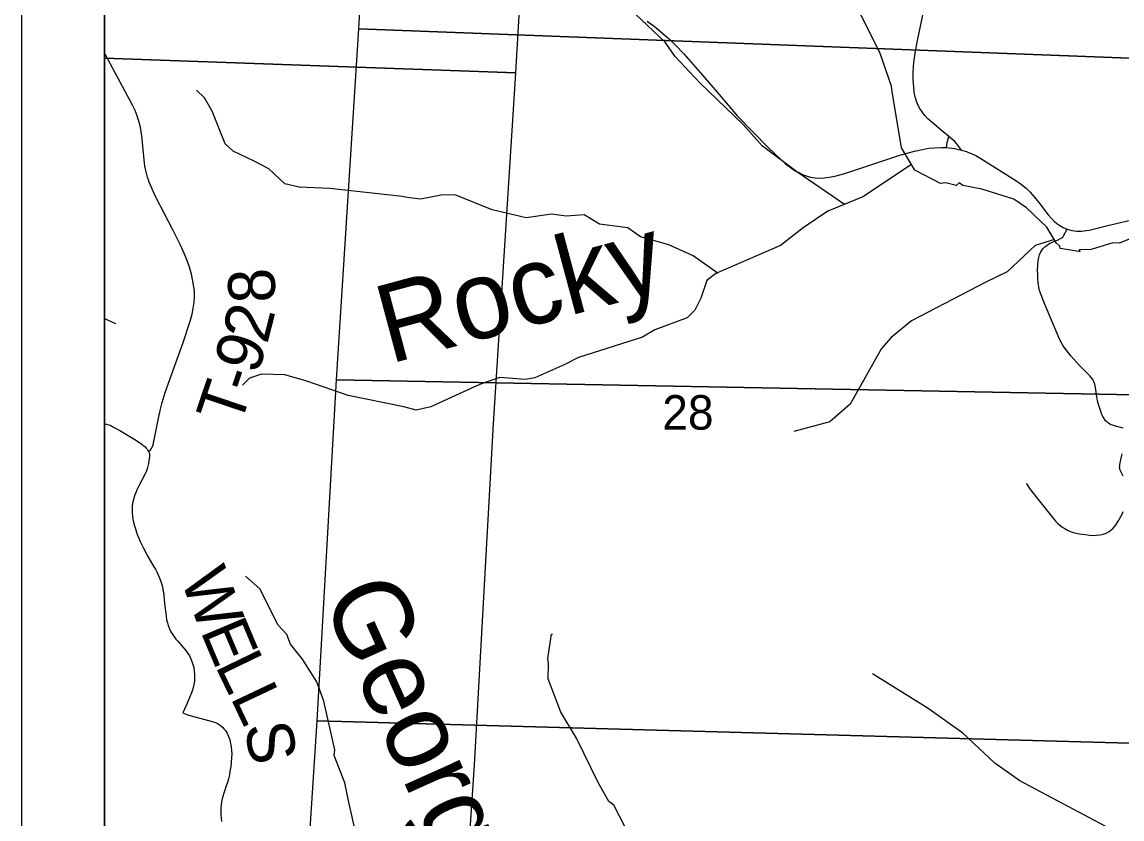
# Model space of a CAD drawing. Extents: x 0 to 34, y 0 to 22.
# Drawn here: x 23.737 to 25.071, y 17.66 to 18.626 of the extents above; entities that cross this region are included whole.
import ezdxf

# ---------------------------------------------------------------- set-up
doc = ezdxf.new("R2010")
doc.units = 0
for name, color, linetype in [('GM_X_County_Road', 7, 'Continuous'), ('GM_X_County_Road_Text', 7, 'Continuous'), ('GM_X_County_Text', 7, 'Continuous'), ('GM_X_Minor_River', 7, 'Continuous'), ('GM_X_Minor_River_Text', 7, 'Continuous'), ('GM_X_Section', 7, 'Continuous'), ('GM_X_Section_Text', 7, 'Continuous'), ('GM_X_State_Shield', 7, 'Continuous'), ('GM_X_Township_Road', 7, 'Continuous'), ('GM_X_Township_Road_Text', 7, 'Continuous'), ('SH_Cut_Line', 7, 'Continuous'), ('SH_Data', 7, 'Continuous')]:
    doc.layers.add(name, color=color, linetype=linetype)

msp = doc.modelspace()

# ---------------------------------------------------------------- linework, layer by layer
at = {"layer": 'GM_X_County_Road'}
for points in [[(24.4956, 18.6269), (24.506, 18.6191), (24.5151, 18.6116), (24.523, 18.6047), (24.5296, 18.5982), (24.5398, 18.5874), (24.5628, 18.5613), (24.583, 18.5378), (24.6046, 18.5119), (24.643, 18.4729), (24.6565, 18.4602), (24.6635, 18.454), (24.669, 18.4498), (24.6752, 18.4456), (24.6802, 18.4428), (24.6848, 18.4407), (24.6895, 18.439), (24.6938, 18.4379), (24.6994, 18.4371), (24.7051, 18.4367), (24.7102, 18.4369), (24.7164, 18.4376), (24.7232, 18.4389), (24.731, 18.441), (24.74, 18.4438), (24.8019, 18.4642), (24.8107, 18.4669), (24.8197, 18.4693), (24.8294, 18.4714), (24.8367, 18.4727), (24.8441, 18.4734), (24.8527, 18.4737), (24.8585, 18.4736), (24.8617, 18.4733), (24.865, 18.4729), (24.8684, 18.4724), (24.8717, 18.4718), (24.8769, 18.4706)], [(24.8769, 18.4706), (24.8798, 18.4697), (24.8829, 18.4687), (24.8854, 18.4678), (24.8886, 18.4665), (24.8914, 18.4652), (24.8942, 18.4639), (24.9001, 18.4605), (24.9425, 18.4338), (24.9497, 18.4287), (24.9551, 18.4244), (24.96, 18.4195), (24.965, 18.414), (24.9707, 18.4071), (24.9819, 18.3922), (24.986, 18.3875), (24.9892, 18.3844), (24.9926, 18.3816), (24.9962, 18.379), (25.0001, 18.3769), (25.0049, 18.3748), (25.0079, 18.3739), (25.0105, 18.3732), (25.0137, 18.3726), (25.0165, 18.3723), (25.0197, 18.3722), (25.0224, 18.3723), (25.0254, 18.3726), (25.0284, 18.3731), (25.0316, 18.3736), (25.056, 18.3795)], [(25.056, 18.3795), (25.0902, 18.3878), (25.1035, 18.3907), (25.112, 18.3923), (25.12, 18.3937), (25.1292, 18.3947), (25.1384, 18.3953), (25.1477, 18.3954), (25.1601, 18.395), (25.2208, 18.3915), (25.3075, 18.3848), (25.3566, 18.3838), (25.3731, 18.3836)], [(23.8372, 18.139), (23.8378, 18.1389), (23.8399, 18.1384), (23.8424, 18.1377), (23.8448, 18.1366), (23.8475, 18.1353), (23.8568, 18.1301), (23.868, 18.1235), (23.8759, 18.1185), (23.8824, 18.114), (23.8837, 18.1131), (23.885, 18.112), (23.8865, 18.1107), (23.8878, 18.1094), (23.8891, 18.1079), (23.8899, 18.1066), (23.8908, 18.1051), (23.8911, 18.1044), (23.8917, 18.1029), (23.8919, 18.1016), (23.892, 18.1002), (23.8918, 18.0986), (23.8915, 18.0967), (23.8905, 18.0907), (23.8896, 18.0858), (23.8888, 18.0832), (23.8879, 18.0806), (23.8871, 18.0788), (23.8784, 18.0628), (23.8769, 18.0596), (23.8755, 18.0564), (23.8741, 18.0527), (23.8729, 18.0488), (23.8717, 18.0442), (23.871, 18.0397), (23.8708, 18.0354), (23.8708, 18.0314), (23.8712, 18.0269), (23.8716, 18.0232), (23.8724, 18.0194), (23.8736, 18.0151), (23.8751, 18.0103), (23.8771, 18.0048), (23.879, 18), (23.8805, 17.9963), (23.8821, 17.9928), (23.8842, 17.9887), (23.89, 17.9778), (23.8973, 17.9654), (23.899, 17.9625), (23.9007, 17.9593), (23.9021, 17.9565), (23.9033, 17.9537), (23.9044, 17.9511), (23.9052, 17.9488), (23.906, 17.9465), (23.9068, 17.9439), (23.9075, 17.9411), (23.9082, 17.9377), (23.9087, 17.9347), (23.9093, 17.9304), (23.9097, 17.9264), (23.9102, 17.921), (23.9112, 17.9116), (23.9119, 17.9062), (23.9125, 17.9013), (23.9135, 17.8975), (23.9145, 17.8944), (23.9161, 17.8905), (23.9179, 17.8868), (23.9201, 17.8832), (23.9221, 17.8802), (23.9239, 17.8778), (23.9261, 17.8752), (23.9332, 17.8673), (23.936, 17.864), (23.9385, 17.8606), (23.9404, 17.8574), (23.9421, 17.8541), (23.9434, 17.8506), (23.9446, 17.8471), (23.9455, 17.8433), (23.9462, 17.839), (23.9465, 17.8354), (23.9466, 17.8311), (23.9463, 17.827), (23.9457, 17.8227), (23.9445, 17.8176), (23.9428, 17.8129), (23.9367, 17.7984), (23.9344, 17.793), (23.9321, 17.7887), (23.9384, 17.7862), (23.9452, 17.784), (23.9652, 17.7789), (23.9689, 17.7778), (23.972, 17.7766), (23.9751, 17.775), (23.978, 17.7731), (23.9803, 17.7712), (23.9822, 17.7693), (23.9841, 17.767), (23.986, 17.7639), (23.9877, 17.7599), (23.9892, 17.7557), (23.9903, 17.7514), (23.991, 17.7471), (23.9914, 17.7428), (23.9916, 17.7386), (23.9914, 17.7343), (23.9909, 17.7282), (23.9904, 17.7229), (23.9895, 17.7177), (23.9887, 17.7132), (23.9877, 17.7084), (23.9864, 17.704), (23.9846, 17.6989), (23.9832, 17.6948), (23.9819, 17.691), (23.9808, 17.6872), (23.9799, 17.6842), (23.9792, 17.6808), (23.9786, 17.6771), (23.9783, 17.6731), (23.9782, 17.6689), (23.9784, 17.6647), (23.9787, 17.661), (23.9793, 17.6567)]]:
    msp.add_lwpolyline(points, dxfattribs=at)
at = {"layer": 'GM_X_County_Text'}
msp.add_lwpolyline([(28.4159, 17.3358), (28.4427, 17.7695), (28.4677, 18.1732), (28.5249, 19.1245), (28.5443, 19.4375), (28.5808, 20.0106), (28.6062, 20.4055), (27.8401, 20.4449), (27.0539, 20.4845), (26.781, 20.4973), (26.0533, 20.5337), (24.4417, 20.6174), (23.8372, 20.6485), (23.8372, 14.4177)], dxfattribs=at)
at = {"layer": 'GM_X_Minor_River'}
msp.add_line((23.8372, 18.2664), (23.8507, 18.2605), dxfattribs=at)
for points in [[(24.7349, 18.4047), (24.6769, 18.444), (24.6355, 18.4754), (24.6121, 18.5015), (24.5592, 18.5522), (24.5292, 18.5843), (24.5172, 18.6014), (24.4673, 18.6486)], [(25.0194, 18.3496), (25.0202, 18.3473), (25.0198, 18.3496), (25.019, 18.3477), (24.9963, 18.3514), (24.996, 18.3541), (24.9918, 18.3583), (24.9804, 18.3772), (24.9555, 18.4004), (24.9403, 18.411), (24.9014, 18.423), (24.8783, 18.4275), (24.8738, 18.431), (24.8704, 18.4275), (24.8579, 18.4309), (24.8515, 18.4301), (24.8201, 18.4464), (24.8125, 18.4593), (24.8042, 18.4734), (24.7928, 18.5417), (24.792, 18.5482), (24.778, 18.5877), (24.7511, 18.642)], [(24.5817, 18.321), (24.5513, 18.3425), (24.5219, 18.3556), (24.4874, 18.3654), (24.4722, 18.3765), (24.4376, 18.3807), (24.419, 18.3919), (24.3971, 18.3903), (24.3794, 18.3928), (24.3486, 18.3885), (24.3077, 18.3981), (24.2636, 18.4158), (24.2478, 18.4164), (24.2204, 18.4112), (24.2042, 18.4132), (24.1982, 18.4141), (24.1104, 18.4238), (24.0734, 18.4257), (24.0562, 18.4297), (24.0367, 18.4478), (24.0188, 18.4571), (23.9935, 18.4693), (23.9836, 18.4783), (23.9677, 18.5179), (23.9584, 18.5338), (23.9489, 18.5432)], [(24.8161, 18.4532), (24.7572, 18.4138), (24.7147, 18.3965), (24.6846, 18.3762), (24.6572, 18.3551), (24.579, 18.3211), (24.5678, 18.3124), (24.5607, 18.2909), (24.5535, 18.2764), (24.5441, 18.2672), (24.5048, 18.2525), (24.4898, 18.2438), (24.4123, 18.219), (24.3958, 18.2108), (24.3594, 18.1945), (24.3476, 18.1926), (24.3167, 18.1951), (24.2964, 18.1881), (24.2868, 18.1839), (24.2332, 18.1594), (24.2153, 18.1554), (24.2003, 18.1593), (24.1327, 18.1732), (24.0825, 18.1904), (24.0559, 18.1981), (24.0276, 18.199), (24.0131, 18.1941), (24.0045, 18.1857)], [(24.9894, 18.3623), (24.966, 18.3551), (24.9321, 18.3231), (24.9064, 18.3103), (24.8162, 18.2638), (24.7914, 18.2433), (24.7796, 18.23), (24.7417, 18.1625), (24.7172, 18.1413), (24.6734, 18.1294)], [(25.0874, 18.3653), (25.0682, 18.3577), (25.0602, 18.3581), (25.0341, 18.35), (25.0194, 18.3496)], [(24.1453, 17.6281), (24.1336, 17.6801), (24.1286, 17.7037), (24.1157, 17.7367), (24.1165, 17.7436), (24.1032, 17.8028), (24.0949, 17.826), (24.0793, 17.8503), (24.0775, 17.8537), (24.0627, 17.8719), (24.0585, 17.8833), (24.0479, 17.8947), (24.0256, 17.9387), (24.0082, 17.9542)], [(24.6672, 17.3811), (24.6449, 17.4107), (24.629, 17.427), (24.6173, 17.4513), (24.5809, 17.501), (24.5779, 17.5048), (24.5469, 17.5329), (24.5325, 17.5484), (24.5268, 17.5591), (24.5204, 17.5708), (24.5064, 17.5864), (24.4897, 17.6183), (24.4753, 17.6376), (24.4549, 17.6767), (24.4492, 17.6812), (24.436, 17.704), (24.4098, 17.7579), (24.3909, 17.7894), (24.3754, 17.8297), (24.3757, 17.8483), (24.375, 17.8544), (24.3795, 17.8837), (24.3806, 17.884)], [(25.0709, 17.6406), (24.9474, 17.706), (24.9171, 17.7275), (24.8785, 17.764), (24.8363, 17.7939), (24.7688, 17.8359)]]:
    msp.add_lwpolyline(points, dxfattribs=at)
at = {"layer": 'GM_X_Section'}
for points in [[(24.2052, 19.6482), (25.2325, 19.5985), (25.1763, 18.5784), (24.1456, 18.6175)], [(24.1456, 18.6175), (25.1763, 18.5784), (25.1509, 18.1729), (24.1185, 18.1922)], [(25.1509, 18.1729), (25.1245, 17.7506), (24.0951, 17.7788), (24.1185, 18.1922)], [(24.0951, 17.7788), (25.1245, 17.7506), (25.1122, 17.5559), (24.0818, 17.5731)]]:
    msp.add_lwpolyline(points, close=True, dxfattribs=at)
at = {"layer": 'GM_X_State_Shield'}
for points in [[(23.8372, 19.6255), (23.8372, 18.5819), (24.3364, 18.5641), (24.396, 19.5948)], [(23.8372, 18.5819), (23.8372, 17.5453), (24.2723, 17.5167), (24.2725, 17.5197), (24.2859, 17.7254), (24.3093, 18.1388), (24.3364, 18.5641)]]:
    msp.add_lwpolyline(points, close=True, dxfattribs=at)
at = {"layer": 'GM_X_Township_Road'}
for points in [[(24.8769, 18.4706), (24.8724, 18.4764), (24.8705, 18.4789), (24.8686, 18.481), (24.8662, 18.4829), (24.8613, 18.487), (24.852, 18.4946), (24.8411, 18.5038), (24.8361, 18.5084), (24.8324, 18.5125), (24.829, 18.5169), (24.8263, 18.521), (24.824, 18.5253), (24.8222, 18.5299), (24.8206, 18.5352), (24.8195, 18.5406), (24.8188, 18.5468), (24.8182, 18.556), (24.8181, 18.5634), (24.8185, 18.5721), (24.8192, 18.5795), (24.8205, 18.588), (24.8233, 18.6033), (24.8303, 18.636)], [(23.8908, 18.1051), (23.893, 18.1074), (23.8941, 18.1089), (23.8951, 18.1105), (23.8959, 18.1125), (23.8966, 18.1152), (23.9027, 18.1457), (23.9036, 18.1496), (23.9042, 18.1524), (23.9048, 18.1549), (23.9073, 18.1648), (23.911, 18.1766), (23.9186, 18.1982), (23.9328, 18.2374), (23.9413, 18.2633), (23.9435, 18.2717), (23.945, 18.279), (23.946, 18.2864), (23.9464, 18.2926), (23.9463, 18.2988), (23.9457, 18.305), (23.9446, 18.3117), (23.9427, 18.3202), (23.9403, 18.3286), (23.9379, 18.3356), (23.9346, 18.3437), (23.9289, 18.3561), (23.9205, 18.3732), (23.9095, 18.3942), (23.9004, 18.4119), (23.8975, 18.4179), (23.8946, 18.4243), (23.8931, 18.428), (23.8916, 18.4318), (23.8905, 18.4346), (23.8896, 18.4377), (23.8886, 18.441), (23.8878, 18.4442), (23.8871, 18.4475), (23.8864, 18.4509), (23.8858, 18.455), (23.8853, 18.4589), (23.883, 18.4837), (23.8824, 18.4884), (23.8818, 18.4923), (23.8812, 18.4959), (23.8804, 18.4999), (23.8798, 18.5028), (23.8789, 18.5057), (23.8778, 18.5094), (23.8768, 18.5122), (23.8756, 18.5153), (23.8743, 18.5184), (23.8707, 18.5257), (23.8671, 18.5326), (23.862, 18.5422), (23.8386, 18.586), (23.8372, 18.5886)], [(24.8585, 18.4736), (24.8596, 18.4793), (24.86, 18.4814), (24.8613, 18.487)], [(25.0728, 18.1334), (25.0646, 18.1355), (25.0623, 18.1362), (25.06, 18.137), (25.0583, 18.1376), (25.0567, 18.1385), (25.0551, 18.1394), (25.0537, 18.1404), (25.0525, 18.1416), (25.0515, 18.1426), (25.0507, 18.1438), (25.0497, 18.1453), (25.0483, 18.1477), (25.0471, 18.1502), (25.0461, 18.1527), (25.043, 18.1624), (25.0418, 18.1667), (25.0408, 18.1715), (25.0402, 18.177), (25.0394, 18.183), (25.039, 18.185), (25.0386, 18.1867), (25.0375, 18.1896), (25.036, 18.1923), (25.0341, 18.1948), (25.0324, 18.1968), (25.0308, 18.1985), (25.0197, 18.21), (25.0095, 18.221), (25.0023, 18.2303), (25.0002, 18.2333), (24.9984, 18.2363), (24.9962, 18.2404), (24.987, 18.2615), (24.9755, 18.2895), (24.9741, 18.293), (24.9729, 18.2959), (24.9721, 18.2985), (24.9712, 18.3015), (24.9706, 18.3044), (24.9701, 18.3076), (24.9698, 18.3106), (24.9695, 18.3138), (24.9692, 18.3196), (24.9691, 18.325), (24.9692, 18.3312), (24.9696, 18.3362), (24.9704, 18.3404), (24.9713, 18.3434), (24.9725, 18.3463), (24.9737, 18.3484), (24.9756, 18.3509), (24.9777, 18.3531), (24.9802, 18.3551), (24.9828, 18.3568), (24.9861, 18.3585), (24.9939, 18.3619), (24.997, 18.3632), (24.9986, 18.3642), (24.9996, 18.3652), (25.0007, 18.3668), (25.0049, 18.3748)], [(25.0727, 18.0754), (25.0694, 18.0828), (25.0689, 18.0841), (25.0687, 18.0849), (25.0686, 18.0857), (25.0686, 18.0865), (25.0687, 18.0876), (25.0688, 18.0885), (25.069, 18.0894), (25.0712, 18.1008), (25.0716, 18.1024)], [(24.9555, 18.0667), (24.9563, 18.065), (24.9571, 18.0635), (24.9594, 18.0603), (24.9697, 18.0471), (24.9844, 18.029), (24.9874, 18.025), (24.9892, 18.0227), (24.9912, 18.0205), (24.9937, 18.0179), (24.9961, 18.016), (24.9986, 18.0139), (25.0012, 18.0123), (25.0033, 18.0111), (25.0054, 18.01), (25.0079, 18.0088), (25.0098, 18.008), (25.0126, 18.0071), (25.0157, 18.0064), (25.0199, 18.0055), (25.0235, 18.0049), (25.027, 18.0045), (25.0316, 18.0039), (25.0364, 18.0036), (25.0407, 18.0037), (25.045, 18.0042), (25.0487, 18.0051), (25.0522, 18.0064), (25.0549, 18.0078), (25.0575, 18.0096), (25.0603, 18.012), (25.0628, 18.0148), (25.0643, 18.0168), (25.0657, 18.0189), (25.0671, 18.0212), (25.0686, 18.0237), (25.07, 18.0264), (25.0715, 18.0294), (25.0728, 18.0325)]]:
    msp.add_lwpolyline(points, dxfattribs=at)
at = {"layer": 'SH_Cut_Line'}
msp.add_lwpolyline([(30.6372, 20.9), (23.8372, 20.9), (23.8372, 14.4177)], dxfattribs=at)
at = {"layer": 'SH_Data'}
for points in [[(23.7372, 21), (30.7372, 21), (30.7372, 14), (23.7372, 14)], [(23.8372, 20.9), (30.6372, 20.9), (30.6372, 14.1), (23.8372, 14.1)]]:
    msp.add_lwpolyline(points, close=True, dxfattribs=at)

# ---------------------------------------------------------------- texts
at = {"layer": 'GM_X_County_Road_Text'}
for s, rotation, p in [('W', 290.9108, (23.9289, 17.9512)), ('E', 292.8581, (23.9532, 17.8877)), ('L', 295.8747, (23.971, 17.8456)), ('L', 295.2837, (23.9895, 17.8075)), ('S', 280.8697, (24.0065, 17.7726))]:
    msp.add_text(s, height=0.0568, rotation=rotation, dxfattribs=at).set_placement(p)
at = {"layer": 'GM_X_Minor_River_Text'}
for s, height, rotation, p in [('Rocky', 0.0947, 14.9959, (24.1829, 18.2112)), ('George', 0.09469, 294.1351, (24.1001, 17.928))]:
    msp.add_text(s, height=height, rotation=rotation, dxfattribs=at).set_placement(p)
at = {"layer": 'GM_X_Section_Text'}
msp.add_text('28', height=0.04186, rotation=0, dxfattribs=at).set_placement((24.5138, 18.1317))
at = {"layer": 'GM_X_Township_Road_Text'}
for s, rotation, p in [('8', 92.7649, (24.045, 18.2865)), ('2', 75.8124, (24.0346, 18.2344)), ('9', 71.9794, (24.0226, 18.1972)), ('-', 71.4456, (24.015, 18.1745)), ('T', 71.3225, (24.0014, 18.1341))]:
    msp.add_text(s, height=0.0568, rotation=rotation, dxfattribs=at).set_placement(p)

doc.saveas('drawing.dxf')
